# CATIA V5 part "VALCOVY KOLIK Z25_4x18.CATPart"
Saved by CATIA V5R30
Part number: VALCOVY KOLIK Z25/4x18
Bounding box of the stored display mesh (mm): x -18 to -0.009, y -2 to 2, z -2 to 2
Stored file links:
  C:\Users\ondra\Desktop\PŘÍLOHA P III\CATIA\VALCOVY KOLIK Z25_4x18.CATPart
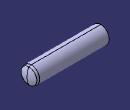
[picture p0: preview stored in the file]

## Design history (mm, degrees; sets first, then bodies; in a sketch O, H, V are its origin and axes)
Set1
  DatumSurface1 to DatumSurface8 "Z25/4x18"
  Join1: Elements (DatumSurface1; DatumSurface2; DatumSurface3; DatumSurface4; DatumSurface5; DatumSurface6; DatumSurface7; DatumSurface8)
Body1 (main body)
  CloseSurface1: CloseElement Join1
